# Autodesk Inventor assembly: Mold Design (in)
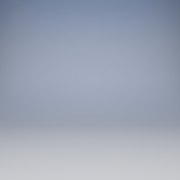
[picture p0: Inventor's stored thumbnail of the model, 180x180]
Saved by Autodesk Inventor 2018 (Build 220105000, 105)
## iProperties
Shininess: 64.0
Length Units: 11272
Angle Units: 11279
Time Units: 11290
Mass Units: 11286
Length Display Precision: 3
Angle Display Precision: 2
Compacted: True
Part Number: Mold Design (in)
Document SubType Name: Assembly
Created: 2002-07
Material: Ogólny
Density: 0.0
Volumn: 0.0
Area: 0.0
PropertySet Name: Model Information
Control State: 0
Master: False
Checked Out: False
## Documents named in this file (1)
- C:\Users\Joffi\Desktop\Templates.Base\English.Base\Mold Design (in).iam
